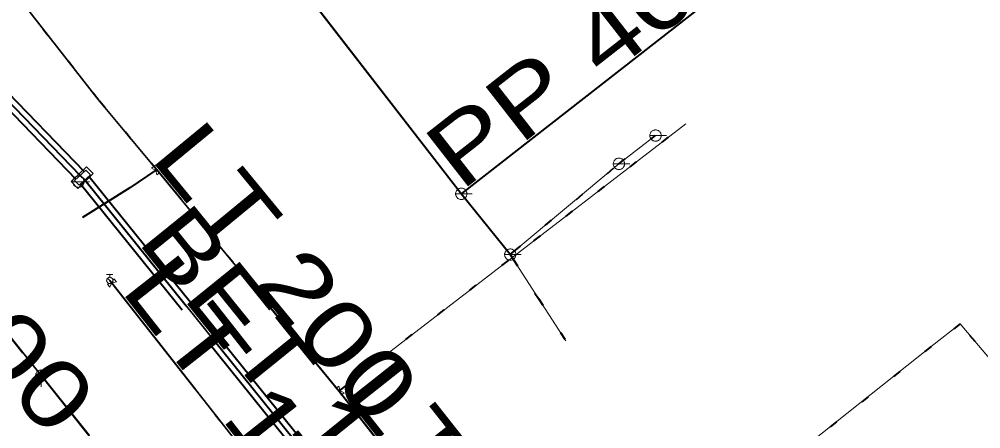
# Model space of a CAD drawing. Extents: x -968691 to -140888, y -1376050 to -879856.
# Drawn here: x -648011.1 to -647839.9, y -1059058.6 to -1058985.7 of the extents above; entities that cross this region are included whole.
import ezdxf
from ezdxf.enums import TextEntityAlignment as Align

# ---------------------------------------------------------------- set-up
doc = ezdxf.new("R2010")
doc.units = 0
doc.header["$LTSCALE"] = 4.8
for name, pattern in [('DASH_DOUBLE_DOT', [9.2, 5, -1.2, 0.3, -1.2, 0.3, -1.2]), ('DOTTED', [1.5, 0.3, -1.2]), ('LONG_DASHED', [7.5, 6, -1.5])]:
    doc.linetypes.add(name, pattern=pattern)
doc.layers.add('1', color=7, linetype='Continuous', lineweight=13)

msp = doc.modelspace()

# ---------------------------------------------------------------- linework, layer by layer
at = {"layer": '1', "linetype": 'LONG_DASHED', "lineweight": 40}
for p, q in [((-648039.943, -1058971.172), (-647999.558, -1059012.827)), ((-648041.556, -1058972.382), (-648001.03, -1059014.182)), ((-648015.562, -1058997.758), (-648000.295, -1059013.505)), ((-648000.295, -1059013.505), (-647999.465, -1059014.325)), ((-647999.465, -1059014.325), (-647931.791, -1059098.158)), ((-647998.723, -1059013.65), (-647933.615, -1059094.305)), ((-648000.206, -1059014.999), (-647935.182, -1059095.55))]:
    msp.add_line(p, q, dxfattribs=at)
at = {"layer": '1', "lineweight": 40}
for p, q in [((-647932.41, -1059016.786), (-647964.558, -1058975.32)), ((-647923.68, -1059027.6), (-647932.41, -1059016.786))]:
    msp.add_line(p, q, dxfattribs=at)
at = {"layer": '1', "lineweight": 35}
for p, q in [((-647932.41, -1059016.786), (-647964.558, -1058975.32)), ((-648015.562, -1058997.758), (-648000.295, -1059013.505)), ((-647954.18, -1059051.95), (-647986.69, -1059012.46)), ((-648000.295, -1059013.505), (-647999.465, -1059014.325)), ((-647999.465, -1059014.325), (-647931.791, -1059098.158)), ((-647923.68, -1059027.6), (-647932.41, -1059016.786)), ((-648025.456, -1059026.328), (-648007.21, -1059049.14)), ((-647995.01, -1059032.19), (-647994.63, -1059032.65)), ((-647994.63, -1059032.65), (-647957.61, -1059079.7)), ((-647971.15, -1059094.31), (-648007.21, -1059049.14)), ((-647918.782, -1059096.747), (-647954.18, -1059051.95))]:
    msp.add_line(p, q, dxfattribs=at)
at = {"layer": '1', "linetype": 'DOTTED', "lineweight": 40}
for p, q in [((-647947.99, -1059047.09), (-647892.4, -1059004.33)), ((-647904.33, -1059011.45), (-647897.81, -1059006.42)), ((-647922.96, -1059026.999), (-647904.33, -1059011.45)), ((-647923.68, -1059027.6), (-647922.96, -1059026.999)), ((-647923.68, -1059027.6), (-647923.172, -1059028.39))]:
    msp.add_line(p, q, dxfattribs=at)
at = {"layer": '1'}
for p, q in [((-647947.99, -1059047.09), (-647892.4, -1059004.33)), ((-647904.33, -1059011.45), (-647897.81, -1059006.42)), ((-647898.818, -1059006.42), (-647895.841, -1059006.42)), ((-647922.96, -1059026.999), (-647904.33, -1059011.45)), ((-647905.338, -1059011.45), (-647902.361, -1059011.45)), ((-647986.69, -1059012.46), (-647986.82, -1059012.58)), ((-648001.599, -1059014.626), (-647998.623, -1059014.626)), ((-647933.418, -1059016.786), (-647930.442, -1059016.786)), ((-647924.688, -1059027.6), (-647921.712, -1059027.6)), ((-647923.68, -1059027.6), (-647922.96, -1059026.999)), ((-647923.68, -1059027.6), (-647923.172, -1059028.39)), ((-647995.569, -1059031.121), (-647994.451, -1059031.121)), ((-647994.615, -1059032.586), (-647995.405, -1059031.795)), ((-647995.01, -1059031.632), (-647995.01, -1059031.121)), ((-647954.01, -1059051.81), (-647947.99, -1059047.09)), ((-648007.21, -1059048.132), (-648007.21, -1059051.108)), ((-647954.18, -1059051.95), (-647954.01, -1059051.81))]:
    msp.add_line(p, q, dxfattribs=at)
at = {"layer": '1', "linetype": 'LONG_DASHED'}
for p, q in [((-648001.9, -1059014.6), (-647999.14, -1059011.96)), ((-648001.3, -1059014.43), (-647999.29, -1059012.58)), ((-647997.95, -1059013.19), (-648000.72, -1059015.83)), ((-647999.29, -1059012.58), (-647998.46, -1059013.41)), ((-647999.14, -1059011.96), (-647997.95, -1059013.19)), ((-648000.72, -1059015.83), (-648001.9, -1059014.6)), ((-648000.47, -1059015.24), (-648001.3, -1059014.43)), ((-647998.46, -1059013.41), (-648000.47, -1059015.24))]:
    msp.add_line(p, q, dxfattribs=at)
at = {"layer": '1', "linetype": 'DASH_DOUBLE_DOT', "lineweight": 40}
for p, q in [((-647986.69, -1059012.46), (-647986.82, -1059012.58)), ((-647954.18, -1059051.95), (-647986.69, -1059012.46)), ((-648025.456, -1059026.328), (-648007.21, -1059049.14)), ((-647995.01, -1059032.19), (-647994.63, -1059032.65)), ((-647994.63, -1059032.65), (-647957.61, -1059079.7)), ((-647954.01, -1059051.81), (-647947.99, -1059047.09)), ((-647971.15, -1059094.31), (-648007.21, -1059049.14)), ((-647954.18, -1059051.95), (-647954.01, -1059051.81)), ((-647918.782, -1059096.747), (-647954.18, -1059051.95))]:
    msp.add_line(p, q, dxfattribs=at)
at = {"layer": '1', "lineweight": 40}
msp.add_lwpolyline([(-647915.525, -1058942.102), (-647902.625, -1058957.89), (-647885.22, -1058979.927), (-647932.41, -1059016.786)], dxfattribs=at)
at = {"layer": '1', "lineweight": 35}
for points in [[(-647915.525, -1058942.102), (-647902.625, -1058957.89), (-647885.22, -1058979.927), (-647932.41, -1059016.786)], [(-647986.69, -1059012.46), (-647997.079, -1059000.002), (-648010.025, -1058983.473)]]:
    msp.add_lwpolyline(points, dxfattribs=at)
at = {"layer": '1', "linetype": 'DOTTED', "lineweight": 40}
for points in [[(-647986.69, -1059012.46), (-647997.079, -1059000.002), (-648010.025, -1058983.473)], [(-647923.172, -1059028.39), (-647918.654, -1059035.411), (-647913.802, -1059042.951)], [(-647812.372, -1059058.499), (-647822.173, -1059065.739), (-647826.94, -1059059.55), (-647843.57, -1059039.941), (-647848.69, -1059043.929), (-647891.45, -1059077.91)]]:
    msp.add_lwpolyline(points, dxfattribs=at)
at = {"layer": '1'}
for points in [[(-647897.81, -1059005.412), (-647897.915, -1059005.418), (-647898.019, -1059005.434), (-647898.121, -1059005.461), (-647898.219, -1059005.499), (-647898.313, -1059005.547), (-647898.401, -1059005.604), (-647898.484, -1059005.671), (-647898.559, -1059005.746), (-647898.625, -1059005.828), (-647898.682, -1059005.915), (-647898.729, -1059006.01), (-647898.767, -1059006.109), (-647898.795, -1059006.21), (-647898.811, -1059006.315), (-647898.818, -1059006.42), (-647898.811, -1059006.525), (-647898.795, -1059006.63), (-647898.767, -1059006.732), (-647898.729, -1059006.83), (-647898.682, -1059006.923), (-647898.625, -1059007.013), (-647898.559, -1059007.095), (-647898.484, -1059007.169), (-647898.401, -1059007.235), (-647898.313, -1059007.293), (-647898.219, -1059007.341), (-647898.121, -1059007.379), (-647898.019, -1059007.406), (-647897.915, -1059007.422), (-647897.81, -1059007.428), (-647897.704, -1059007.422), (-647897.599, -1059007.406), (-647897.498, -1059007.379), (-647897.4, -1059007.341), (-647897.305, -1059007.293), (-647897.217, -1059007.235), (-647897.135, -1059007.169), (-647897.06, -1059007.095), (-647896.994, -1059007.013), (-647896.937, -1059006.923), (-647896.888, -1059006.83), (-647896.85, -1059006.732), (-647896.824, -1059006.63), (-647896.808, -1059006.525), (-647896.802, -1059006.42), (-647896.808, -1059006.315), (-647896.824, -1059006.21), (-647896.85, -1059006.109), (-647896.888, -1059006.01), (-647896.937, -1059005.915), (-647896.994, -1059005.828), (-647897.06, -1059005.746), (-647897.135, -1059005.671), (-647897.217, -1059005.604), (-647897.305, -1059005.547), (-647897.4, -1059005.499), (-647897.498, -1059005.461), (-647897.599, -1059005.434), (-647897.704, -1059005.418)], [(-647904.33, -1059010.442), (-647904.435, -1059010.448), (-647904.539, -1059010.464), (-647904.641, -1059010.491), (-647904.739, -1059010.529), (-647904.833, -1059010.577), (-647904.921, -1059010.634), (-647905.004, -1059010.701), (-647905.079, -1059010.776), (-647905.145, -1059010.858), (-647905.202, -1059010.945), (-647905.249, -1059011.04), (-647905.287, -1059011.139), (-647905.315, -1059011.24), (-647905.331, -1059011.345), (-647905.338, -1059011.45), (-647905.331, -1059011.555), (-647905.315, -1059011.66), (-647905.287, -1059011.762), (-647905.249, -1059011.86), (-647905.202, -1059011.953), (-647905.145, -1059012.043), (-647905.079, -1059012.125), (-647905.004, -1059012.199), (-647904.921, -1059012.265), (-647904.833, -1059012.323), (-647904.739, -1059012.371), (-647904.641, -1059012.409), (-647904.539, -1059012.436), (-647904.435, -1059012.452), (-647904.33, -1059012.458), (-647904.224, -1059012.452), (-647904.119, -1059012.436), (-647904.018, -1059012.409), (-647903.92, -1059012.371), (-647903.825, -1059012.323), (-647903.737, -1059012.265), (-647903.655, -1059012.199), (-647903.58, -1059012.125), (-647903.514, -1059012.043), (-647903.457, -1059011.953), (-647903.408, -1059011.86), (-647903.37, -1059011.762), (-647903.344, -1059011.66), (-647903.328, -1059011.555), (-647903.322, -1059011.45), (-647903.328, -1059011.345), (-647903.344, -1059011.24), (-647903.37, -1059011.139), (-647903.408, -1059011.04), (-647903.457, -1059010.945), (-647903.514, -1059010.858), (-647903.58, -1059010.776), (-647903.655, -1059010.701), (-647903.737, -1059010.634), (-647903.825, -1059010.577), (-647903.92, -1059010.529), (-647904.018, -1059010.491), (-647904.119, -1059010.464), (-647904.224, -1059010.448)], [(-647986.088, -1059012.966), (-647986.646, -1059013.389), (-647986.994, -1059011.771), (-647987.552, -1059012.194)], [(-648000.591, -1059013.618), (-648000.696, -1059013.624), (-648000.8, -1059013.64), (-648000.902, -1059013.668), (-648001.001, -1059013.706), (-648001.095, -1059013.753), (-648001.183, -1059013.811), (-648001.265, -1059013.877), (-648001.34, -1059013.952), (-648001.406, -1059014.034), (-648001.464, -1059014.122), (-648001.511, -1059014.216), (-648001.549, -1059014.315), (-648001.577, -1059014.417), (-648001.593, -1059014.521), (-648001.599, -1059014.626), (-648001.593, -1059014.731), (-648001.577, -1059014.836), (-648001.549, -1059014.938), (-648001.511, -1059015.036), (-648001.464, -1059015.13), (-648001.406, -1059015.219), (-648001.34, -1059015.301), (-648001.265, -1059015.375), (-648001.183, -1059015.441), (-648001.095, -1059015.499), (-648001.001, -1059015.547), (-648000.902, -1059015.585), (-648000.8, -1059015.612), (-648000.696, -1059015.628), (-648000.591, -1059015.634), (-648000.486, -1059015.628), (-648000.381, -1059015.612), (-648000.279, -1059015.585), (-648000.181, -1059015.547), (-648000.087, -1059015.499), (-647999.998, -1059015.441), (-647999.916, -1059015.375), (-647999.842, -1059015.301), (-647999.776, -1059015.219), (-647999.718, -1059015.13), (-647999.67, -1059015.036), (-647999.632, -1059014.938), (-647999.605, -1059014.836), (-647999.589, -1059014.731), (-647999.583, -1059014.626), (-647999.589, -1059014.521), (-647999.605, -1059014.417), (-647999.632, -1059014.315), (-647999.67, -1059014.216), (-647999.718, -1059014.122), (-647999.776, -1059014.034), (-647999.842, -1059013.952), (-647999.916, -1059013.877), (-647999.998, -1059013.811), (-648000.087, -1059013.753), (-648000.181, -1059013.706), (-648000.279, -1059013.668), (-648000.381, -1059013.64), (-648000.486, -1059013.624)], [(-647932.41, -1059015.778), (-647932.515, -1059015.784), (-647932.619, -1059015.8), (-647932.721, -1059015.828), (-647932.82, -1059015.866), (-647932.914, -1059015.913), (-647933.002, -1059015.971), (-647933.084, -1059016.037), (-647933.159, -1059016.112), (-647933.225, -1059016.194), (-647933.283, -1059016.282), (-647933.33, -1059016.376), (-647933.368, -1059016.475), (-647933.396, -1059016.577), (-647933.412, -1059016.681), (-647933.418, -1059016.786), (-647933.412, -1059016.891), (-647933.396, -1059016.996), (-647933.368, -1059017.098), (-647933.33, -1059017.196), (-647933.283, -1059017.29), (-647933.225, -1059017.379), (-647933.159, -1059017.461), (-647933.084, -1059017.535), (-647933.002, -1059017.601), (-647932.914, -1059017.659), (-647932.82, -1059017.707), (-647932.721, -1059017.745), (-647932.619, -1059017.772), (-647932.515, -1059017.788), (-647932.41, -1059017.794), (-647932.305, -1059017.788), (-647932.2, -1059017.772), (-647932.098, -1059017.745), (-647932, -1059017.707), (-647931.906, -1059017.659), (-647931.817, -1059017.601), (-647931.735, -1059017.535), (-647931.661, -1059017.461), (-647931.595, -1059017.379), (-647931.537, -1059017.29), (-647931.489, -1059017.196), (-647931.451, -1059017.098), (-647931.424, -1059016.996), (-647931.408, -1059016.891), (-647931.402, -1059016.786), (-647931.408, -1059016.681), (-647931.424, -1059016.577), (-647931.451, -1059016.475), (-647931.489, -1059016.376), (-647931.537, -1059016.282), (-647931.595, -1059016.194), (-647931.661, -1059016.112), (-647931.735, -1059016.037), (-647931.817, -1059015.971), (-647931.906, -1059015.913), (-647932, -1059015.866), (-647932.098, -1059015.828), (-647932.2, -1059015.8), (-647932.305, -1059015.784)], [(-647923.68, -1059026.592), (-647923.785, -1059026.598), (-647923.889, -1059026.614), (-647923.991, -1059026.642), (-647924.09, -1059026.68), (-647924.184, -1059026.727), (-647924.272, -1059026.785), (-647924.354, -1059026.851), (-647924.429, -1059026.926), (-647924.495, -1059027.008), (-647924.553, -1059027.096), (-647924.6, -1059027.19), (-647924.638, -1059027.289), (-647924.666, -1059027.391), (-647924.682, -1059027.495), (-647924.688, -1059027.6), (-647924.682, -1059027.705), (-647924.666, -1059027.81), (-647924.638, -1059027.912), (-647924.6, -1059028.01), (-647924.553, -1059028.104), (-647924.495, -1059028.193), (-647924.429, -1059028.275), (-647924.354, -1059028.349), (-647924.272, -1059028.415), (-647924.184, -1059028.473), (-647924.09, -1059028.521), (-647923.991, -1059028.559), (-647923.889, -1059028.586), (-647923.785, -1059028.602), (-647923.68, -1059028.608), (-647923.575, -1059028.602), (-647923.47, -1059028.586), (-647923.368, -1059028.559), (-647923.27, -1059028.521), (-647923.176, -1059028.473), (-647923.087, -1059028.415), (-647923.005, -1059028.349), (-647922.931, -1059028.275), (-647922.865, -1059028.193), (-647922.807, -1059028.104), (-647922.759, -1059028.01), (-647922.721, -1059027.912), (-647922.694, -1059027.81), (-647922.678, -1059027.705), (-647922.672, -1059027.6), (-647922.678, -1059027.495), (-647922.694, -1059027.391), (-647922.721, -1059027.289), (-647922.759, -1059027.19), (-647922.807, -1059027.096), (-647922.865, -1059027.008), (-647922.931, -1059026.926), (-647923.005, -1059026.851), (-647923.087, -1059026.785), (-647923.176, -1059026.727), (-647923.27, -1059026.68), (-647923.368, -1059026.642), (-647923.47, -1059026.614), (-647923.575, -1059026.598)], [(-647994.451, -1059032.191), (-647994.46, -1059032.094), (-647994.485, -1059032), (-647994.526, -1059031.912), (-647994.582, -1059031.832), (-647994.651, -1059031.763), (-647994.731, -1059031.707), (-647994.819, -1059031.666), (-647994.913, -1059031.641), (-647995.01, -1059031.632), (-647995.107, -1059031.641), (-647995.201, -1059031.666), (-647995.289, -1059031.707), (-647995.369, -1059031.763), (-647995.438, -1059031.832), (-647995.494, -1059031.912), (-647995.535, -1059032), (-647995.56, -1059032.094), (-647995.569, -1059032.191), (-647995.56, -1059032.288), (-647995.535, -1059032.382), (-647995.494, -1059032.47), (-647995.438, -1059032.55), (-647995.369, -1059032.619), (-647995.289, -1059032.675), (-647995.201, -1059032.716), (-647995.107, -1059032.741), (-647995.01, -1059032.749), (-647994.913, -1059032.741), (-647994.819, -1059032.716), (-647994.731, -1059032.675), (-647994.651, -1059032.619), (-647994.582, -1059032.55), (-647994.526, -1059032.47), (-647994.485, -1059032.382), (-647994.46, -1059032.288)], [(-647994.274, -1059031.903), (-647993.829, -1059032.443), (-647995.431, -1059032.857), (-647994.986, -1059033.397)], [(-648006.202, -1059049.14), (-648006.208, -1059049.035), (-648006.224, -1059048.931), (-648006.252, -1059048.829), (-648006.29, -1059048.73), (-648006.337, -1059048.636), (-648006.395, -1059048.548), (-648006.461, -1059048.466), (-648006.536, -1059048.391), (-648006.618, -1059048.325), (-648006.706, -1059048.267), (-648006.8, -1059048.22), (-648006.899, -1059048.182), (-648007.001, -1059048.154), (-648007.105, -1059048.138), (-648007.21, -1059048.132), (-648007.315, -1059048.138), (-648007.42, -1059048.154), (-648007.522, -1059048.182), (-648007.62, -1059048.22), (-648007.714, -1059048.267), (-648007.803, -1059048.325), (-648007.885, -1059048.391), (-648007.959, -1059048.466), (-648008.025, -1059048.548), (-648008.083, -1059048.636), (-648008.131, -1059048.73), (-648008.169, -1059048.829), (-648008.196, -1059048.931), (-648008.212, -1059049.035), (-648008.218, -1059049.14), (-648008.212, -1059049.245), (-648008.196, -1059049.35), (-648008.169, -1059049.452), (-648008.131, -1059049.55), (-648008.083, -1059049.644), (-648008.025, -1059049.733), (-648007.959, -1059049.815), (-648007.885, -1059049.889), (-648007.803, -1059049.955), (-648007.714, -1059050.013), (-648007.62, -1059050.061), (-648007.522, -1059050.099), (-648007.42, -1059050.126), (-648007.315, -1059050.142), (-648007.21, -1059050.148), (-648007.105, -1059050.142), (-648007.001, -1059050.126), (-648006.899, -1059050.099), (-648006.8, -1059050.061), (-648006.706, -1059050.013), (-648006.618, -1059049.955), (-648006.536, -1059049.889), (-648006.461, -1059049.815), (-648006.395, -1059049.733), (-648006.337, -1059049.644), (-648006.29, -1059049.55), (-648006.252, -1059049.452), (-648006.224, -1059049.35), (-648006.208, -1059049.245)], [(-647953.269, -1059052.178), (-647953.816, -1059052.615), (-647954.204, -1059051.005), (-647954.751, -1059051.442)]]:
    msp.add_lwpolyline(points, close=True, dxfattribs=at)
at = {"layer": '1', "linetype": 'DASH_DOUBLE_DOT', "lineweight": 40}
msp.add_lwpolyline([(-647986.82, -1059012.58), (-647991.46, -1059015.7), (-647999.89, -1059021)], dxfattribs=at)
at = {"layer": '1'}
for points in [[(-647986.82, -1059012.58), (-647991.46, -1059015.7), (-647999.89, -1059021)], [(-647923.172, -1059028.39), (-647918.654, -1059035.411), (-647913.802, -1059042.951)], [(-647812.372, -1059058.499), (-647822.173, -1059065.739), (-647826.94, -1059059.55), (-647843.57, -1059039.941), (-647848.69, -1059043.929), (-647891.45, -1059077.91)]]:
    msp.add_lwpolyline(points, dxfattribs=at)
for centre in [(-647986.82, -1059012.58), (-647994.63, -1059032.65), (-647954.01, -1059051.81)]:
    msp.add_circle(centre, 0.132, dxfattribs=at)

# ---------------------------------------------------------------- texts
for s, rotation, width, p in [('PP 400', 37.993, 1.25, (-647906.576, -1058996.227)), ('ETE 200', 312.29, 1.25, (-648031.769, -1059031.711)), ('LT 200', 309.463, 1.25, (-647968.143, -1059034.516)), ('BET 1600', 308.912, 1.2, (-647963.398, -1059058.526)), ('LT 100', 308.196, 1.25, (-647973.968, -1059058.423)), ('LT 200', 308.315, 1.25, (-647934.317, -1059076.604))]:
    msp.add_text(s, height=12, rotation=rotation, dxfattribs=dict(at, width=width)).set_placement(p, align=Align.CENTER)

doc.saveas('drawing.dxf')
